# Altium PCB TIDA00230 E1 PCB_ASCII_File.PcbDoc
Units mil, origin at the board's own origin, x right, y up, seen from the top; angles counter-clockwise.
Board outline 1000 x 1000 mil, 2 copper layers (Top Layer, Bottom Layer), stack 62 mil thick; 50 components, 26 nets, 149 pads, 37 vias.
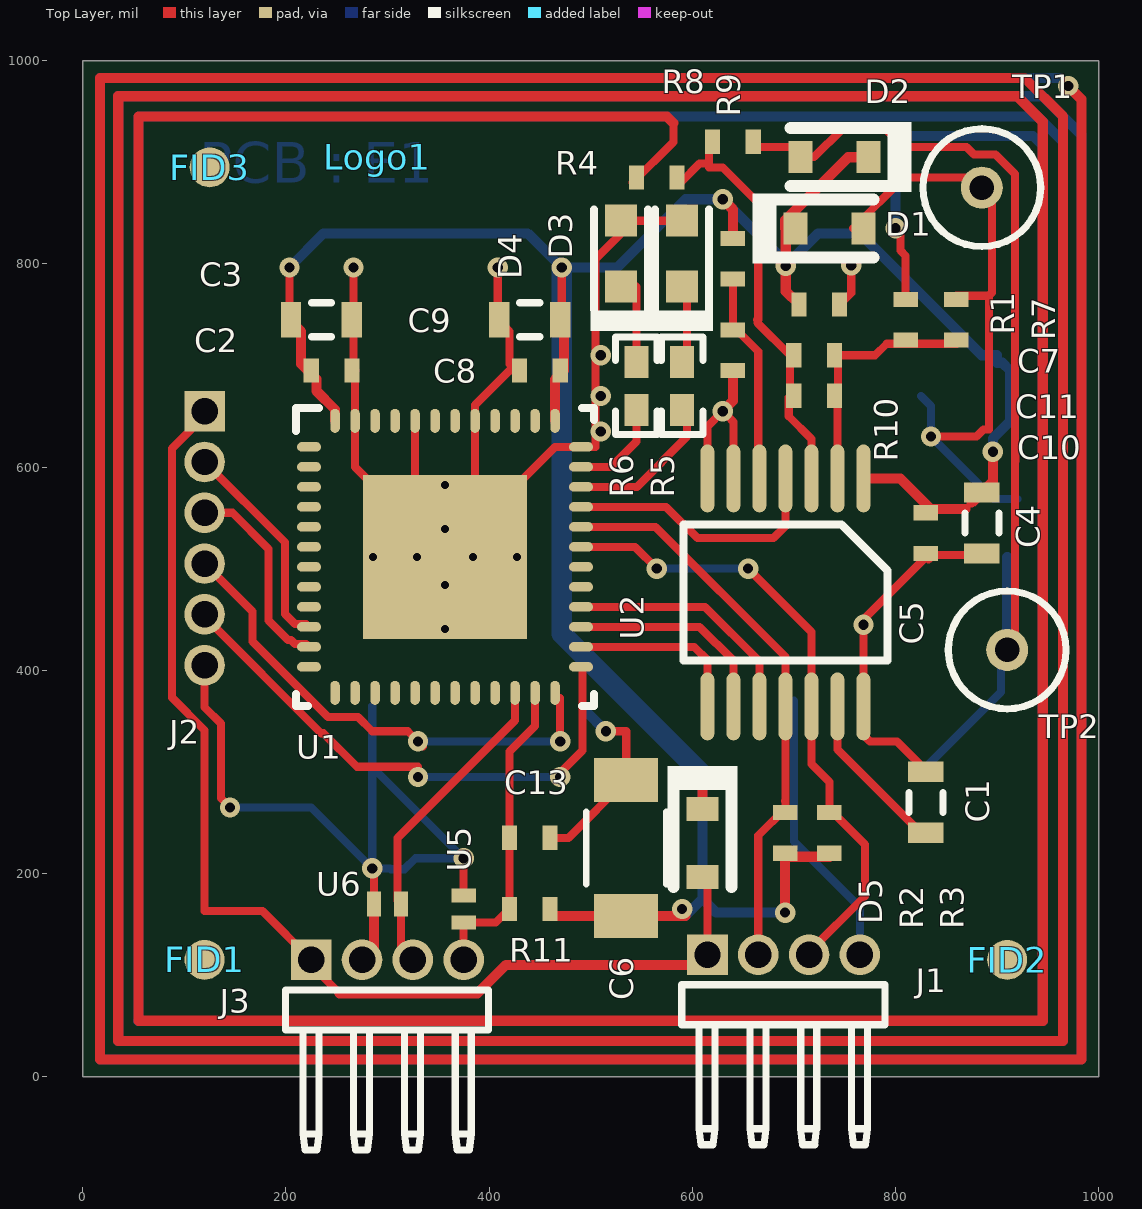
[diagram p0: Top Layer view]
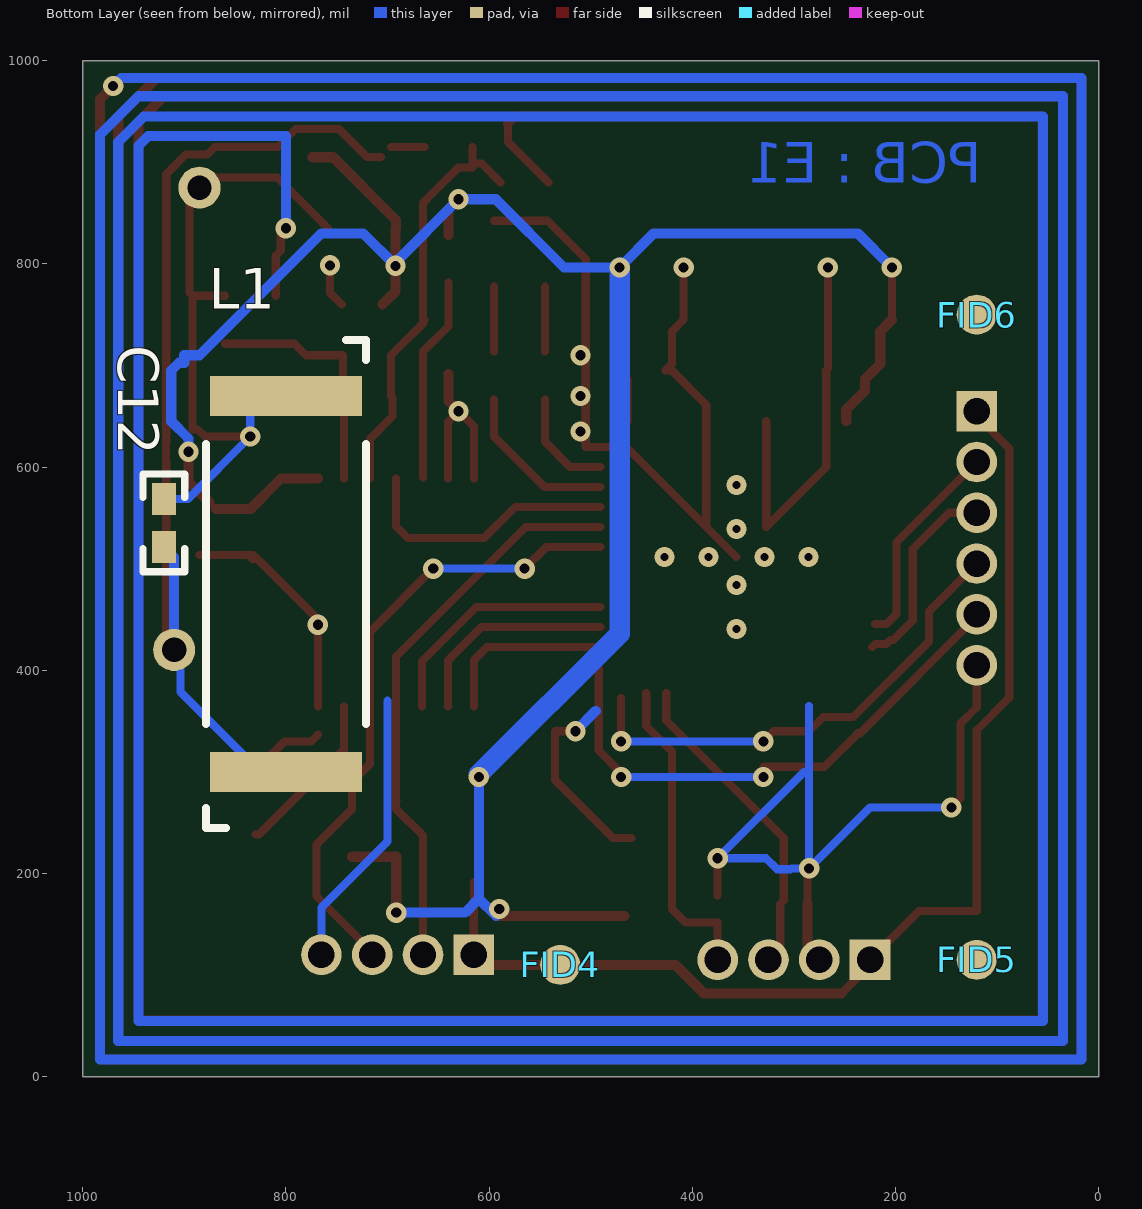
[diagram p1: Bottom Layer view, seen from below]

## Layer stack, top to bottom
Top Layer: signal copper 1.4
Dielectric: core 59.2, FR-4, Dk 4.8
Bottom Layer: signal copper 1.4

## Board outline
0,0 0,1000 1000,1000 1000,0

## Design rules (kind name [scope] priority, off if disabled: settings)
AssemblyTestPointUsage [All] p0 off: scope1count=1 scope1_0_kind=Board scope1_0_value=Board scope2count=1 scope2_0_kind=Board scope2_0_value=Board commentlength=0
AssemblyTestPointUsage [All] p1 off:
AssemblyTestpoint [All] p0 off: scope1count=1 scope1_0_kind=Board scope1_0_value=Board scope2count=1 scope2_0_kind=Board scope2_0_value=Board commentlength=0
AssemblyTestpoint [All] p1 off: testpointundercomponent=TRUE minsize=40 maxsize=100 preferedsize=60 minholesize=0 maxholesize=40 preferedholesize=32 testpointgrid=1 usegrid=TRUE gridtolerance=0.01 allowsidetop=TRUE allowsidebottom=TRUE
Clearance [All] p0: scope1count=1 scope1_0_kind=Board scope1_0_value=Board scope2count=1 scope2_0_kind=Board scope2_0_value=Board commentlength=0 gap=4.92
Clearance [All] p1: gap=4.92
ComponentClearance [All] p0: scope1count=1 scope1_0_kind=Board scope1_0_value=Board scope2count=1 scope2_0_kind=Board scope2_0_value=Board commentlength=0 gap=10 collisioncheckmode=3
DiffPairsRouting [All] p0: scope1count=1 scope1_0_kind=Board scope1_0_value=Board scope2count=1 scope2_0_kind=Board scope2_0_value=Board commentlength=0
DiffPairsRouting [All] p1: maxlimit=393.7 minlimit=4.92 mostfreqgap=5.91 maxuncoupledlength=500
FabricationTestPointUsage FabricationTestPointUsage_1 [All] p0 off: scope1count=1 scope1_0_kind=Board scope1_0_value=Board scope2count=1 scope2_0_kind=Board scope2_0_value=Board commentlength=0 valid=0 allowmultiple=FALSE
FabricationTestPointUsage FabricationTestPointUsage_1 [All] p1 off: valid=0 allowmultiple=FALSE
FabricationTestpoint FabricationTestpoint_1 [All] p0 off: scope1count=1 scope1_0_kind=Board scope1_0_value=Board scope2count=1 scope2_0_kind=Board scope2_0_value=Board commentlength=0 side=3 testpointundercomponent=TRUE minsize=40 maxsize=100 preferedsize=60 minholesize=0 maxholesize=40 preferedholesize=32 testpointgrid=1
FabricationTestpoint FabricationTestpoint_1 [All] p1 off: side=3 testpointundercomponent=TRUE minsize=40 maxsize=100 preferedsize=60 minholesize=0 maxholesize=40 preferedholesize=32 testpointgrid=1 allowsidetop=TRUE allowsidebottom=TRUE usegrid=TRUE gridtolerance=0.01
FanoutControl Fanout_BGA [All] p0 off: scope1count=1 scope1_0_kind=Board scope1_0_value=Board scope2count=1 scope2_0_kind=Board scope2_0_value=Board commentlength=69 // Protel DXP Scope 1 Expression Was: IsBGA   Fanout_BGA (Default Rule)
FanoutControl Fanout_LCC [All] p0 off: scope1count=1 scope1_0_kind=Board scope1_0_value=Board scope2count=1 scope2_0_kind=Board scope2_0_value=Board commentlength=69 // Protel DXP Scope 1 Expression Was: IsLCC   Fanout_LCC (Default Rule)
FanoutControl Fanout_SOIC [All] p0 off: scope1count=1 scope1_0_kind=Board scope1_0_value=Board scope2count=1 scope2_0_kind=Board scope2_0_value=Board commentlength=71 // Protel DXP Scope 1 Expression Was: IsSOIC   Fanout_SOIC (Default Rule)
FanoutControl Fanout_Small [All] p0 off: scope1count=1 scope1_0_kind=Board scope1_0_value=Board scope2count=1 scope2_0_kind=Board scope2_0_value=Board commentlength=84 // Protel DXP Scope 1 Expression Was: (CompPinCount < 5)   Fanout_Small (Default Rule)
FanoutControl Fanout_Default [All] p0: scope1count=1 scope1_0_kind=Board scope1_0_value=Board scope2count=1 scope2_0_kind=Board scope2_0_value=Board commentlength=30 // Fanout_Default (Default Rule)
Height [All] p0: scope1count=1 scope1_0_kind=Board scope1_0_value=Board scope2count=1 scope2_0_kind=Board scope2_0_value=Board commentlength=0
HoleSize [All] p0: scope1count=1 scope1_0_kind=Board scope1_0_value=Board scope2count=1 scope2_0_kind=Board scope2_0_value=Board commentlength=0 absolutevalues=TRUE maxlimit=236.22 minlimit=7.87 maxpercent=80.000 minpercent=20.000
HoleSize FabricationTestpoint [All] p0 off: scope1count=1 scope1_0_kind=Board scope1_0_value=Board scope2count=1 scope2_0_kind=Board scope2_0_value=Board commentlength=0 absolutevalues=TRUE maxlimit=100 minlimit=1 maxpercent=80.000 minpercent=20.000
HoleSize FabricationTestPointUsage [All] p0 off: scope1count=1 scope1_0_kind=Board scope1_0_value=Board scope2count=1 scope2_0_kind=Board scope2_0_value=Board commentlength=0 absolutevalues=TRUE maxlimit=100 minlimit=1 maxpercent=80.000 minpercent=20.000
HoleSize [All] p1: absolutevalues=TRUE maxlimit=236.22 minlimit=7.87 maxpercent=80.000 minpercent=20.000
HoleSize FabricationTestpoint [All] p2 off: absolutevalues=TRUE maxlimit=100 minlimit=1 maxpercent=80.000 minpercent=20.000
HoleSize FabricationTestPointUsage [All] p3 off: absolutevalues=TRUE maxlimit=100 minlimit=1 maxpercent=80.000 minpercent=20.000
HoleToHoleClearance [All] p0: scope1count=1 scope1_0_kind=Board scope1_0_value=Board scope2count=1 scope2_0_kind=Board scope2_0_value=Board commentlength=0
LayerPairs [All] p0: scope1count=1 scope1_0_kind=Board scope1_0_value=Board scope2count=1 scope2_0_kind=Board scope2_0_value=Board commentlength=0 enforce=TRUE
MinimumSolderMaskSliver [All] p0: scope1count=1 scope1_0_kind=Board scope1_0_value=Board scope2count=1 scope2_0_kind=Board scope2_0_value=Board commentlength=0
MinimumSolderMaskSliver MinimumSolderMaskSliver_mcv [All] p0: scope1count=1 scope1_0_kind=Board scope1_0_value=Board scope2count=1 scope2_0_kind=Board scope2_0_value=Board commentlength=0
MinimumSolderMaskSliver MinimumSolderMaskSliver_mcv [All] p2: minsoldermaskwidth=5
NetAntennae [All] p0: scope1count=1 scope1_0_kind=Board scope1_0_value=Board scope2count=1 scope2_0_kind=Board scope2_0_value=Board commentlength=0
PasteMaskExpansion [All] p0: scope1count=1 scope1_0_kind=Board scope1_0_value=Board scope2count=1 scope2_0_kind=Board scope2_0_value=Board commentlength=0 expansion=0
PlaneClearance [All] p0: scope1count=1 scope1_0_kind=Board scope1_0_value=Board scope2count=1 scope2_0_kind=Board scope2_0_value=Board commentlength=0 clearance=19.68
PlaneClearance [All] p1: clearance=19.68
PlaneConnect [All] p0: scope1count=1 scope1_0_kind=Board scope1_0_value=Board scope2count=1 scope2_0_kind=Board scope2_0_value=Board commentlength=0 planeconnectstyle=Relief reliefexpansion=15.75 reliefentries=4 reliefconductorwidth=5.91 reliefairgap=5.91
PlaneConnect [All] p1: planeconnectstyle=Relief reliefexpansion=15.75 reliefentries=4 reliefconductorwidth=5.91 reliefairgap=5.91
PolygonConnect [All] p0: scope1count=1 scope1_0_kind=Board scope1_0_value=Board scope2count=1 scope2_0_kind=Board scope2_0_value=Board commentlength=0 connectstyle=Relief reliefconductorwidth=5.91 reliefentries=4 polygonreliefangle="90 Angle"
PolygonConnect [All] p1: connectstyle=Relief reliefconductorwidth=5.91 reliefentries=4 polygonreliefangle="90 Angle" airgapwidth=10
RoutingCorners [All] p0: scope1count=1 scope1_0_kind=Board scope1_0_value=Board scope2count=1 scope2_0_kind=Board scope2_0_value=Board commentlength=0 cornerstyle=45-Degree minsetback=49.21 maxsetback=49.21
RoutingCorners [All] p1: cornerstyle=45-Degree minsetback=49.21 maxsetback=49.21
RoutingLayers [All] p0: scope1count=1 scope1_0_kind=Board scope1_0_value=Board scope2count=1 scope2_0_kind=Board scope2_0_value=Board commentlength=0 top layer=Automatic bottom layer=Automatic
RoutingPriority [All] p0: scope1count=1 scope1_0_kind=Board scope1_0_value=Board scope2count=1 scope2_0_kind=Board scope2_0_value=Board commentlength=0
RoutingTopology [All] p0: scope1count=1 scope1_0_kind=Board scope1_0_value=Board scope2count=1 scope2_0_kind=Board scope2_0_value=Board commentlength=0 topology=Shortest
RoutingVias [All] p0: scope1count=1 scope1_0_kind=Board scope1_0_value=Board scope2count=1 scope2_0_kind=Board scope2_0_value=Board commentlength=0 holewidth=11.81 width=23.62 viastyle="Through Hole" minholewidth=7.87 minwidth=17.72 maxholewidth=17.72 maxwidth=29.53
RoutingVias [All] p1: holewidth=11.81 width=23.62 viastyle="Through Hole" minholewidth=7.87 minwidth=17.72 maxholewidth=17.72 maxwidth=29.53
ShortCircuit [All] p0: scope1count=1 scope1_0_kind=Board scope1_0_value=Board scope2count=1 scope2_0_kind=Board scope2_0_value=Board commentlength=0 allowed=FALSE
SilkToSilkClearance [All] p0: scope1count=1 scope1_0_kind=Board scope1_0_value=Board scope2count=1 scope2_0_kind=Board scope2_0_value=Board commentlength=0
SilkscreenOverComponentPads [All] p0: scope1count=1 scope1_0_kind=Board scope1_0_value=Board scope2count=1 scope2_0_kind=Board scope2_0_value=Board commentlength=0
SilkscreenOverComponentPads SilkscreenOverComponentPads_mcv [All] p0: scope1count=1 scope1_0_kind=Board scope1_0_value=Board scope2count=1 scope2_0_kind=Board scope2_0_value=Board commentlength=0
SilkscreenOverComponentPads SilkscreenOverComponentPads_mcv [All] p1: minsilkscreentomaskgap=5
SilkscreenOverComponentPads [All] p2: minsilkscreentomaskgap=10
SolderMaskExpansion [All] p0: scope1count=1 scope1_0_kind=Board scope1_0_value=Board scope2count=1 scope2_0_kind=Board scope2_0_value=Board commentlength=0 expansion=2.95
SolderMaskExpansion [All] p1: expansion=2.95
UnRoutedNet [All] p0: scope1count=1 scope1_0_kind=Board scope1_0_value=Board scope2count=1 scope2_0_kind=Board scope2_0_value=Board commentlength=0
Width [All] p0: scope1count=1 scope1_0_kind=Board scope1_0_value=Board scope2count=1 scope2_0_kind=Board scope2_0_value=Board commentlength=0 maxlimit=393.7 minlimit=4.92 preferedwidth=5.91
Width [All] p1: maxlimit=393.7 minlimit=4.92 preferedwidth=5.91
18 further rules are at their usual default settings.

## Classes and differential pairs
component class Logo: Logo1
component class "TIDA00230 Hardware_ANSI-B": FID1 FID2 FID3 FID4 FID5 FID6 Logo1 ZZ1 ZZ2 ZZ3 ZZ4
component class FiducialMark: FID1 FID2 FID3 FID4 FID5 FID6
component class AssemblyNote: ZZ1 ZZ2 ZZ3 ZZ4
component class "TIDA00230 Sheet 1": C1 C2 C3 C4 C5 C6 C7 C8 C9 C10 C11 C12 C13 D1 D2 D3 D4 D5 J1 J2 J3 L1 R1 R2 R3 R4 R5 R6 R7 R8 R9 R10 R11 TP1 TP2 U1 U2 U5 U6

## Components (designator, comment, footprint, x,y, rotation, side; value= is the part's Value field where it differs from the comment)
C1 "GRM188R71E474KA12D" 0603S 830,270 r90 top
C2 "GRM155R71C104KA88D" 0402S 245,695 r0 top
C3 "GRM188R71C105KA12D" 0603S 235,745 r0 top
C4 "GRM188R71C105KA12D" 0603S 885,545 r270 top
C5 "GRM155R71C104KA88D" 0402S 830,535 r270 top
C6 "C3216X5R1A107M160AC" 1206_190 535,225 r90 top
C7 "CL05A106MP5NUNC" 0402S 725,760 r0 top
C8 "GRM155R71C104KA88D" 0402S 450,695 r180 top
C9 "GRM188R71C105KA12D" 0603S 440,745 r180 top
C10 "GRM1555C1H390JA01D" 0402S 720,670 r180 top
C11 "GRM1555C1E6R2CA01D" 0402S 720,710 r180 top
C12 "GRM1555C1H390JA01D" 0402 920,545 r270 bottom
C13 "DNP" 0402S 440,235 r0 top
D1 "CDBU0130L" SOD-523F 735,835 r0 top
D2 "CDBU0130L" SOD-523F 740,905 r180 top
D3 "SML-311DTT86" SML-31_Orange 590,810 r90 top
D4 "SML-311DTT86" SML-31_Orange 530,810 r90 top
D5 "CDBU0130L" SOD-523F 610,230 r270 top
FID1 "Fiducial" Fiducial10-20 120,115 r0 top
FID2 "Fiducial" Fiducial10-20 910,115 r0 top
FID3 "Fiducial" Fiducial10-20 125,895 r0 top
FID4 "Fiducial" Fiducial10-20 530,110 r180 bottom
FID5 "Fiducial" Fiducial10-20 120,115 r180 bottom
FID6 "Fiducial" Fiducial10-20 120,750 r180 bottom
J1 "I2C Interface Connector" Sullins_GRPB041VWCN 690,120 r0 top
J2 "SPI Connector (Back-up)" Sullins_GRPB061VWCN 120,530 r270 top
J3 "Debug and Programming Interface" Sullins_GRPB041VWCN 300,115 r0 top
L1 "NFC Antenna - 3uH" PREMO_SDTR1103-HF2 800,485 r90 bottom
Logo1 "Texas Instruments" TI_Symbol_Overlay_Small 290,905 r0 top
R1 "CRCW04020000Z0ED" 0402S 810,745 r270 top
R2 "CRCW04024K75FKED" 0402S 691.41,240 r270 top
R3 "CRCW04024K75FKED" 0402S 735,240 r270 top
R4 "CRCW04020000Z0ED" 0402S 565,885 r180 top
R5 "CRCW04021K00FKED" 0402 590,680 r270 top
R6 "CRCW04021K00FKED" 0402 545,680 r270 top
R7 "CRCW04020000Z0ED" 0402S 860,745 r270 top
R8 "CRCW04020000Z0ED" 0402S 640,920 r180 top
R9 "CRCW04020000Z0ED" 0402S 640,805 r90 top
R10 "CRCW04020000Z0ED" 0402S 640,715 r90 top
R11 "CRCW040247K0JNED" 0402S 440,165 r0 top
TP1 "5000" Keystone5000 885,875 r0 top
TP2 "5000" Keystone5000 910,420 r0 top
U1 "MSP430FR5969IRGZ" RGZ0048B 356.69,511.61 r0 top
U2 "RF430CL330HCPW" PW0014A_N 691.69,476.61 r270 top
U5 "TPD1E10B06DPYR" DPY0002A_N 375,165 r90 top
U6 "TPD1E10B06DPYR" DPY0002A_N 300,170 r180 top
ZZ1 "This Assembly Note is for PCB labels only" AssemblyNoteLabel 265,3938 r0 top
ZZ2 "These assemblies are ESD sensitive, ESD precautions shall be observed." AssemblyNote 265,3829.11 r0 top
ZZ3 "These assemblies must be clean and free from flux and all contaminants. Use of no clean flux is not acceptable." AssemblyNote 265,3740.56 r0 top
ZZ4 "These assemblies must comply with workmanship standards IPC-A-610 Class 2, unless otherwise specified." AssemblyNote 265,3652 r0 top

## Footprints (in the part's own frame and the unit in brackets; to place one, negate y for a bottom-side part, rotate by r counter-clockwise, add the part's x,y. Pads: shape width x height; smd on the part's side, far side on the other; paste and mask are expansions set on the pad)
0402 [mm] "0402 from SM-752 data"
  rect 0.8x0.6 smd: 1(-0.6,0) 2(0.6,0)
  silkscreen extent -1.22,-0.52 1.22,0.52
0402S [mil] "Based on C0402S footprint from PADS legacy"
  rect 15x24 smd: 1(-20,0) 2(20,0)
0603S [mil]
  rect 20x35 smd: 1(-30,0) 2(30,0)
  silkscreen extent -10,-17 10,17
1206_190 [mm] "1206_190"
  rect 1.1x1.6 smd: 1(-1.7,0) 2(1.7,0)
  silkscreen extent -0.9,-1 0.9,1
AssemblyNote [mil] "Assembly Note"
AssemblyNoteLabel [mil] "Assembly Note for PCB Labels"
DPY0002A_N [mm] "DFN, 2-Leads, Body 1.0x0.6x0.4mm, IPC Medium Density"
  rect 0.35x0.62 smd: 1(-0.34,0) 2(0.34,0)
Fiducial10-20 [mm]
  round 1 smd paste-0.5 mask+0.5: 1(0,0)
Keystone5000 [mm] "For Keystone 500x miniature loop terminals"
  round 1.05 hole 0.61: 1(0,0)
  silkscreen extent -1.47,-1.47 1.47,1.47
PREMO_SDTR1103-HF2 [mm] "Premo"
  rect 1x3.8 smd: 1(-4.7,0) 2(4.7,0)
  silkscreen extent -6.1,-2 6.1,2
PW0014A_N [mm] "TSOP, 14-Leads, Body 5x4.4mm, Pitch 0.65mm, IPC Medium Density"
  oval 1.7x0.35 smd: 1(-2.85,1.95) 2(-2.85,1.3) 3(-2.85,0.65) 4(-2.85,0) 5(-2.85,-0.65) 6(-2.85,-1.3) 7(-2.85,-1.95) 8(2.85,-1.95) 9(2.85,-1.3) 10(2.85,-0.65) 11(2.85,0) 12(2.85,0.65) 13(2.85,1.3) 14(2.85,1.95)
  silkscreen extent -1.7,-2.55 1.7,2.55
RGZ0048B [mm] "QFN, 48-Leads, Body 7x7mm, Pitch 0.5mm, Thermal Pad 5.15x5.15mm, TI Recommended"
  oval 0.6x0.24 smd: 1(-3.4,2.75) 2(-3.4,2.25) 3(-3.4,1.75) 4(-3.4,1.25) 5(-3.4,0.75) 6(-3.4,0.25) 7(-3.4,-0.25) 8(-3.4,-0.75) 9(-3.4,-1.25) 10(-3.4,-1.75) 11(-3.4,-2.25) 12(-3.4,-2.75) 25(3.4,-2.75) 26(3.4,-2.25) 27(3.4,-1.75) 28(3.4,-1.25) 29(3.4,-0.75) 30(3.4,-0.25) 31(3.4,0.25) 32(3.4,0.75) 33(3.4,1.25) 34(3.4,1.75) 35(3.4,2.25) 36(3.4,2.75)
  oval 0.24x0.6 smd: 13(-2.75,-3.4) 14(-2.25,-3.4) 15(-1.75,-3.4) 16(-1.25,-3.4) 17(-0.75,-3.4) 18(-0.25,-3.4) 19(0.25,-3.4) 20(0.75,-3.4) 21(1.25,-3.4) 22(1.75,-3.4) 23(2.25,-3.4) 24(2.75,-3.4) 37(2.75,3.4) 38(2.25,3.4) 39(1.75,3.4) 40(1.25,3.4) 41(0.75,3.4) 42(0.25,3.4) 43(-0.25,3.4) 44(-0.75,3.4) 45(-1.25,3.4) 46(-1.75,3.4) 47(-2.25,3.4) 48(-2.75,3.4)
  rect 4.1x4.1 smd paste-2.575: 49(0,0)
  silkscreen extent -3.72,-3.72 3.72,3.72
SML-31_Orange [mm] "Rohm"
  rect 0.8x0.8 smd: 1(-0.825,0) 2(0.825,0)
  silkscreen extent -1.93,-0.77 1.1,0.77
SOD-523F [mm] "COMCHIP"
  rect 0.6x0.8 smd paste-0.05: 1(-0.85,0) 2(0.85,0)
  silkscreen extent -1.92,-0.87 1.1,0.87
Sullins_GRPB041VWCN [mil] "Sullins"
  rect 40x40 hole 26 mask+3: 1(-75,0)
  round 40 hole 26 mask+3: 2(-25,0) 3(25,0) 4(75,0)
  silkscreen extent -100,-187 100,-30
Sullins_GRPB061VWCN [mil] "Sullins"
  rect 40x40 hole 26 mask+3: 1(-125,0)
  round 40 hole 26 mask+3: 2(-75,0) 3(-25,0) 4(25,0) 5(75,0) 6(125,0)
TI_Symbol_Overlay_Small [mil]

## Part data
C1: "CAP, CERM, 0.47uF, 25V, +/-10%, X7R, 0603"
C2 C5 C8: "CAP, CERM, 0.1uF, 16V, +/-10%, X7R, 0402"
C3 C4 C9: "CAP, CERM, 1uF, 16V, +/-10%, X7R, 0603"
C6: "CAP, CERM, 100uF, 10V, +/-20%, X5R, 1206_190"
C7: "CAP, CERM, 10uF, 10V, +/-20%, X5R, 0402"
C10 C12: "CAP, CERM, 39pF, 50V, +/-5%, C0G/NP0, 0402"
C11: "CAP, CERM, 6.2pF, 25V, +/-5%, C0G/NP0, 0402"
C13: library part GRM155R70J222KA01D, "CAP, CERM, 2200pF, 6.3V, +/-10%, X7R, 0402"
D1 D2 D5: "Diode, Schottky, 35V, 0.1A, SOD-523F"
D3 D4: "LED, Orange, SMD"
FID1 FID2 FID3 FID4 FID5 FID6: "Fiducial mark.  There is nothing to buy or mount."
J1 J3: library part GRPB041VWCN-RC, "Header, 50mil, 4x1, R/A, TH"
J2: library part GRPB061VWCN-RC, "Header, 50mil, 6x1, R/A, TH"
L1: library part SDTR1103-HF2-0003K, "Inductor, Wirewound, 3uH, 0.46 ohm, SMD"
Logo1: library part TI_Logo, "Texas Instrument Corporate Signature"
R1 R4 R7 R8 R9 R10: "RES, 0 ohm, 5%, 0.063W, 0402"
R2 R3: "RES, 4.75k ohm, 1%, 0.063W, 0402"
R5 R6: "RES, 1.00k ohm, 1%, 0.063W, 0402"
R11: "RES, 47k ohm, 5%, 0.063W, 0402"
TP1 TP2: "Test Point, Miniature, Red, TH"
U1: "Mixed Signal Microcontroller, RGZ0048B"
U2: "DYNAMIC NFC INTERFACE TRANSPONDER, PW0014A"
U5 U6: "ESD in 0402 Package with 10 pF Capacitance and 6 V Breakdown, 1 Channel, -40 to +125 degC, 2-pin X2SON (DPY), Green (RoHS & no Sb/Br)"
ZZ1: library part AssemblyNoteLabel
ZZ2 ZZ3 ZZ4: library part AssemblyNote

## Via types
v1: diameter 20, hole 10, Top Layer to Bottom Layer, 29 vias
v2: diameter 19.68, hole 7.87, Top Layer to Bottom Layer, 8 vias

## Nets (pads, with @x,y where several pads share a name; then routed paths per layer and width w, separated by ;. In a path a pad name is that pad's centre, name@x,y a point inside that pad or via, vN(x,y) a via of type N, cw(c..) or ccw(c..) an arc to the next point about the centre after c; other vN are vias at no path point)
ANT1: C10.1 C11.1 R1.2 R7.2 U2.2 | length 242.6
  Top Layer w8: U2.2 742.87,669.25 743.62,670 743.62,710 780,710 791.38,721.38 810,721.38 R7.2@860,721.38
ANT2: C10.2 C11.2 R4.1 R8.2 U2.3 | length 410.6
  Top Layer w7.99: 616.38,898.62 R8.2@616.38,915 ; 655,870 665,860
  Top Layer w8: R4.1@588.62,880 607.24,898.62 616.38,898.62 ; 616.38,895 630,895 655,870 ; 665,860 665,745 663.81,745 664.41,744.41 664.41,741.97 696.38,710 696.38,670 695,668.62 695,650 717.28,627.72 U2.3
GND_SYSTEM: C1.2 C2.2 C3.2 C4.2 C5.2 C6.2 C7.2 C8.2 C9.2 C13.2 D3.2 D4.2 J1.4 J2.6 J3.2 R10.1 U1.36 U1.41 U1.44 U1.47 U1.49 U2.6 U2.7 U2.14 U5.2 U6.2 | length 2948
  Top Layer w8: J2.6 120,363.63 136,347.63 136,274 v1(145,265) ; v1(266.5,796.5) 266.5,697.13 C2.2@268.62,695 ; C2.2@268.11,694.49 U1.47 268.11,600.2 327.17,541.14 U1.44 ; v1(285,205) 286.61,203.39 U6.2 ; U1.49 U1.49@386.22,541.14 ; U5.2 v1(375,215) ; v1(408.5,796.5) 408.5,745 420,733.5 420,701.38 426.38,695 420,695 386.22,661.22 U1.41 U1.49@386.22,541.14 ; C13.2 478.07,235 C6.2 535,340 v1(515,340) ; D3.2@595,842.48 542.48,842.48 504.88,804.88 504.88,619.88 U1.36 464.96,619.88 U1.49@386.22,541.14 ; U2.7 614.92,639.92 v1(630,655) ; v1@635.51,649.49 640.51,644.49 U2.6 ; C7.2 756.5,771.5 v1(756.5,798.5) ; U2.14@768.46,336.54 775,330 801.5,330 C1.2@830,301.5 ; U2.14 v1(768.46,444.84) ; v1@768.46,449.84 C5.2@830,511.38 ; C5.2@832.13,513.5 C4.2@885,513.5 ; C5.2@832.5,508.88 C5.2@835,511.38
  Top Layer w10: J3.2@286.61,126.61 U6.2 ; v1(630,655) 640,665 R10.1@640,691.38
  Bottom Layer w8: v1(145,265) 225,265 v1(285,205) ; 285,365 v1(285,205) ; 290,300 v1(375,215) 327.43,215 316.63,204.2 303.37,204.2 302.57,205 v1(285,205) ; 700,370 700,231.41 765,166.41 J1.4
  Bottom Layer w10: 495,360 v1(515,340)
  other v1: 510,635 510,670 510,710
  other v2: 356.69,440.75 356.69,484.05 285.83,511.61 329.13,511.61 384.25,511.61 427.56,511.61 356.69,539.17 356.69,582.48
I2C_SCL: J1.2 R2.1 U1.32 U2.11 | length 568.4
  Top Layer w8: U1.32 563.86,541.14 691.69,413.31 U2.11 R2.1@691.69,263.62 ; J1.2@665,110 665,237.22 R2.1@691.41,263.62 ; 691.41,271.41 691.41,271.5
I2C_SDA: J1.3 R3.1 U1.31 U2.12 | length 633.8
  Top Layer w8: U1.31 543.54,521.46 v1(565,500) ; v1(655,500) 717.28,437.72 U2.12 717.28,307.72 735,290 735,263.62 770,228.62 770,177.52 715,122.52 J1.3@715,110
  Bottom Layer w8: v1(565,500) v1(655,500)
NetC1_1: C1.1 U2.13 | length 164
  Top Layer w8: U2.13 742.87,322.13 826.5,238.5 C1.1@830,238.5
NetC12_1: C12.1 D1.2 L1.2 R7.1 TP1.1 | length 630.9
  Top Layer w8: D1.2@758.46,835 808.46,885 875,885 TP1.1 895,865 895,771.62 892,768.62 ; v1(835,630) 879.75,630 886.75,637 892,637 892,768.62 ; R7.1@860,768.62 892,768.62
  Bottom Layer w8: L1.2@825,670.04 835,660.04 835,640.35 ; v1(835,630) 896.38,568.62 C12.1
NetC12_2: C12.2 D2.2 L1.1 R8.1 TP2.1 | length 975.2
  Top Layer w7.99: TP2.1@917.67,433.93 917.67,605.7 917.86,605.89 917.86,624.11 917.67,624.3 917.67,753.06
  Top Layer w8: R8.1@663.62,915 D2.2@696.54,915 ; D2.2 720,905 747.75,932.75 790.25,932.75 807.99,915 870,915 877.33,907.67 898.53,907.67 917.67,888.53 917.67,753.06
  Bottom Layer w8: L1.1@825,299.96 903.74,378.7 TP2.1@903.74,420
  Bottom Layer w10: TP2.1@903.74,420 910,426.26 C12.2@910,511.38
NetD3_1: D3.1 R5.1 | length 63.9
  Top Layer w8: R5.1@595,713.62 D3.1@595,777.52
NetD4_1: D4.1 R6.1 | length 63.9
  Top Layer w8: R6.1@545,713.62 D4.1@545,777.52
NetR5_2: R5.2 U1.34 | length 161.3
  Top Layer w8: U1.34 545.51,580.51 595,630 R5.2@595,666.38
NetR6_2: R6.2 U1.35 | length 106.1
  Top Layer w8: U1.35 520.2,600.2 545,625 R6.2@545,666.38
NetR9_1: R9.1 R10.2 U2.5 | length 201.8
  Top Layer w7.99: R9.1@640,781.38 640,738.62 665,713.62 U2.5@665,589.92
PCB_ANT: R1.1 R4.2 | length 22180.9
  Top Layer w7.99: R4.2@541.38,880 581.38,920 581.38,938.62 ; v1@805,830 805,813 810,808 R1.1@810,768.62
  Top Layer w10: 581.38,938.62 575,945 55,945 55,55 945,55 945,940 920,965 35,965 35,35 965,35 965,945 927,983 17,983 17,17 983,17 983,962 v1(970,975)
  Bottom Layer w10: 54.73,54.95 944.95,54.95 944.95,916.42 935.45,925.91 800,925.91 800,845 ; 54.86,55.08 54.86,944.89 ; 54.97,945 940,945 965,920 965,35 35,35 35,965 945,965 983,927 983,17 17,17 17,983 962,983 v1(970,975)
  other v1: 800,835
RF430_CS: U1.27 U2.9 | length 208.8
  Top Layer w8: U1.27 607.28,442.72 640.51,409.49 U2.9
RF430_IRQ: U1.26 U2.8 | length 175.4
  Top Layer w8: U1.26 601.97,423.03 614.92,410.08 U2.8
RF430_RST: U1.33 U2.4 | length 265.9
  Top Layer w8: U1.33 574.17,560.83 605,530 680,530 691.69,541.69 U2.4
RF430_SCK: U1.28 U2.10 | length 242.2
  Top Layer w8: U1.28 612.6,462.4 666.1,408.9 U2.10
SBWTCK: J3.3 U1.22 U6.1 | length 295.6
  Top Layer w8: U6.1@310,173.39 310,235 425.59,350.59 U1.22 ; J3.3@313.39,126.61 U6.1
SBWTDIO: C13.1 J3.4 R11.1 U1.23 U5.1 | length 310.4
  Top Layer w8: J3.4 U5.1 406.61,151.61 R11.1 C13.1 420,320 445.28,345.28 U1.23
UCSIA0_CLK: J2.3 U1.11 | length 198.8
  Top Layer w8: J2.3 147.37,555 183.02,519.35 183.02,448.85 202.19,429.68 205.14,429.68 208.82,425.99 219.87,425.99 U1.11
UCSIA0_SIMO: J2.4 U1.24 | length 489.6
  Top Layer w8: J2.4 167.02,457.98 167.02,428.42 241.5,353.94 271.06,353.94 285,340 320,340 v1(330,330) v1@335,325 ; v1(470,330) 470,372.72
  Bottom Layer w8: v1(330,330) v1(470,330)
UCSIA0_SOMI: J2.5 U1.25 | length 539.4
  Top Layer w8: J2.5 120,452.82 234.87,337.94 237.06,337.94 270,305 330,305 v1(330,295) ; v1(470,295) 470,298.89 492,320.89 U1.25@492,401.9
  Bottom Layer w8: v1(330,295) v1(470,295)
UCSIA0_STE: J2.2 U1.10 | length 207.2
  Top Layer w8: J2.2 199.02,525.98 199.02,455.47 208.82,445.68 U1.10@219.87,445.68
VCC: C2.1 C3.1 C4.1 C5.1 C6.1 C7.1 C8.1 C9.1 D1.1 D2.1 D5.1 R2.2 R3.2 R9.2 R11.2 U1.37 U1.48 U2.1 | length 2725.8
  Top Layer w8: C3.1@203.5,745 v1(203.5,796.5) ; C9.1@471.5,745 v1(471.5,796.5)
  Top Layer w10: C3.1@203.5,745 215,733.5 215,701.38 230,686.38 230,675 248.43,656.57 U1.48 ; U1.37 464.96,686.34 473.62,695 473.62,742.87 C9.1@471.5,745 ; R11.2@466.93,158.07 C6.1 v1@593.07,158.07 ; D5.1 v1(610,295) ; v1(630,863.62) 640,853.62 R9.2@640,828.62 ; v1(691.41,161.41) 691.41,216.38 R3.2@735,216.38 ; D1.1@691.54,835 691.54,843.07 753.46,905 D2.1 ; D1.1@692,834.54 v1(692,798) 692,773 C7.1 ; U2.1 804.8,588.82 835,558.62 868.62,558.62 ; C4.1@875,565 895.87,585.87 v1(895.87,615)
  Bottom Layer w10: v1(203.5,796.5) 237.01,830 437.99,830 v1(471.5,796.5) 526.25,796.5 593.37,863.62 v1(630,863.62) v1@692,801.62 ; v1@593.07,158.07 610,175 ; v1(610,295) 610,175 ; v1(691.41,161.41) 623.59,161.41 610,175 ; v1(692,798) 724,830 765,830 885,710 900,710 900,702.72 905.19,702.72 912.8,695.11 912.8,644.97 895.87,628.03 v1(895.87,615)
  Bottom Layer w20: v1(471.5,796.5) 471.5,436.03 v1@610,297.53
  other v1: 590,165
VCC_SYSTEM: D5.2 J1.1 J2.1 J3.1 | length 1137.3
  Top Layer w7.99: J1.1 615.07,120.07 615.07,167.25 615,167.32 D5.2@615,191.54
  Top Layer w8: J2.1 120,650.25 88,618.25 88,373 120,341 120,163.03 176.97,163.03 J3.1 225,110 253,82
  Top Layer w10: 253,82 388.67,82 416.67,110 605,110 J1.1
pads on no net: FID1.1 FID2.1 FID3.1 FID4.1 FID5.1 FID6.1 U1.1 U1.2 U1.3 U1.4 U1.5 U1.6 U1.7 U1.8 U1.9 U1.12 U1.13 U1.14 U1.15 U1.16 U1.17 U1.18 U1.19 U1.20 U1.21 U1.29 U1.30 U1.38 U1.39 U1.40 U1.42 U1.43 U1.45 U1.46

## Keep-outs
Keep-Out Layer:
  text ".Layer_Name" at 577,-858.49 h60

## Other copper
Top Layer:
  text ".Layer_Name" at 577,-858.49 h60
Bottom Layer:
  text "PCB : E1" at 115,880 h40
  text ".Layer_Name" at 577,-858.49 h60

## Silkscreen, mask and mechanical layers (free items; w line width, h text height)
Top Overlay:
  text ".Layer_Name" at 577,-858.49 h60
Bottom Overlay:
  text ".Layer_Name" at 577,-858.49 h60
Top Paste:
  text ".Layer_Name" at 577,-858.49 h60
Bottom Paste:
  text ".Layer_Name" at 577,-858.49 h60
Top Solder:
  text ".Layer_Name" at 577,-858.49 h60
  text ".Layer_Name" at 577,-858.49 h60
Bottom Solder:
  text ".Layer_Name" at 577,-858.49 h60
Drill Guide:
  text ".Layer_Name" at 577,-858.49 h60
M1 Board Outline:
  the board outline again, w10
  text ".Layer_Name" at 577,-858.49 h60
M2 Board Dimensions:
  rectangle: -0.5,-285.5 124.5,-160.5
  rectangle: 124.5,-410.5 499.5,-285.5
  lines w7: -0.5,-285.5 999.5,-285.5 ; 124.5,-410.5 124.5,-160.5 ; 249.5,-410.5 249.5,-160.5 ; 499.5,-410.5 499.5,-160.5 ; 749.5,-410.5 749.5,-160.5 ; -0.5,-410.5 999.5,-410.5 999.5,-160.5 -0.5,-160.5 -0.5,-410.5
  text ".Layer_Name" at 577,-858.49 h60
M3 3D STEP Top:
  text ".Layer_Name" at 577,-858.49 h60
M4 3D STEP Bottom:
  text ".Layer_Name" at 577,-858.49 h60
M5 Assembly Top:
  lines w10: -292,-930.17 6308,-930.17 ; -292,-726.83 6310,-726.83 ; -292,-523.5 -292,-1133.5 3713,-1133.5 6310,-1133.5 6310,-523.5 -291.5,-523.5 -291.5,-1133.5 1284,-1133.5 ; 2173,-1133.5 2173,-523.5 ; 3440,-726.83 3440,-523.5 ; 4280,-726.83 4280,-523.5 ; 4902,-1140 4902,-937.17
  text "COMPONENTS MARKED 'DNP' SHOULD NOT BE POPULATED." at 1153.5,-318.5 h60
  text "ASSEMBLY VARIANT:" at 1153,-434 h60
  text ".VariantName" at 2189,-434 h60
  text "PCB VIEWED FROM TOP SIDE" at -228.5,-655.67 h60
  text "BOARD #:" at 2248,-655.67 h60
  text ".PRJ_Number" at 2793.5,-655.67 h60
  text "REV:" at 3638,-655.67 h60
  text ".PCB_Rev" at 3929.5,-655.67 h60
  text "SVN REV:" at 4476,-655.67 h60
  text ".VersionControl_RevNumber" at 4982,-655.67 h60
  text "IGNORE ->" at -228.5,-858.49 h60
  text "PLOT NAME =" at -228.5,-1064.34 h60
  text ".plot_File_Name" at 577,-1064.34 h60
  text "GENERATED    :" at 2250,-1064.34 h60
  text ".Print_Date" at 3119.5,-1064.34 h60
  text ".Print_Time" at 3848.5,-1064.34 h60
  text "TEXAS INSTRUMENTS" at 5113,-1064.34 h60
M6 Assembly Bottom:
  lines w10: -292.5,-727.33 6309.5,-727.33 ; -290.5,-930.67 6309.5,-930.67 ; 1115.5,-1140.5 1115.5,-937.67 ; 1737.5,-727.33 1737.5,-524 ; 2577.5,-727.33 2577.5,-524 ; 3844.5,-1134 3844.5,-524 ; 4733.5,-1134 6309,-1134 6309,-524 -292.5,-524 -292.5,-1134 2304.5,-1134 6309.5,-1134 6309.5,-524
  text "COMPONENTS MARKED 'DNP' SHOULD NOT BE POPULATED." at 6102,-318 h60
  text ".VariantName" at 5058,-434 h60
  text "ASSEMBLY VARIANT:" at 6097,-434 h60
  text ".VersionControl_RevNumber" at 1035.5,-656.17 h60
  text "SVN REV:" at 1541.5,-656.17 h60
  text ".PCB_Rev" at 2088,-656.17 h60
  text "REV:" at 2379.5,-656.17 h60
  text ".PRJ_Number" at 3224,-656.17 h60
  text "BOARD #:" at 3769.5,-656.17 h60
  text "PCB VIEWED FROM BOTTOM SIDE" at 6246,-656.17 h60
  text "IGNORE ->" at 2547.85,-858.49 h60
  text "TEXAS INSTRUMENTS" at 904.5,-1064.84 h60
  text ".Print_Time" at 2169,-1064.84 h60
  text ".Print_Date" at 2898,-1064.84 h60
  text "GENERATED    :" at 3767.5,-1064.84 h60
  text ".plot_File_Name" at 5440.5,-1064.84 h60
  text "PLOT NAME =" at 6246,-1064.84 h60
M9 Title Sheet:
  lines w10: -491.5,1041.5 -291.5,1041.5 ; -491.5,3416.5 -291.5,3416.5 ; -491.5,5791.5 -291.5,5791.5 ; 2008.5,-1333.5 2008.5,-1133.5 ; 2008.5,7966.5 2008.5,8166.5 ; 4508.5,-1333.5 4508.5,-1133.5 ; 4508.5,7966.5 4508.5,8166.5 ; 6321,-1133.5 6321,-523.5 11303.5,-523.5 ; 7008.5,-1333.5 7008.5,-1133.5 ; 7008.5,7966.5 7008.5,8166.5 ; 9508.5,-1333.5 9508.5,-1133.5 ; 9508.5,7966.5 9508.5,8166.5 ; 11303.5,-1133.5 11303.5,-523.5 ; 11303.5,-823.5 14303.5,-823.5 ; 11303.5,-223.5 14303.5,-223.5 ; 11304.5,370.5 14304.5,370.5 ; 12008.5,-1333.5 12008.5,-1133.5 ; 12008.5,7966.5 12008.5,8166.5 ; 12808.5,-1123.5 12808.5,-523.5 ; 14303.5,-523.5 11303.5,-523.5 ; 14303.5,76.5 11303.5,76.5 ; 14308.5,66.5 14308.5,-1133.5 ; 14308.5,871 11304.5,871 11303.5,871 11303.5,370.5 11303.5,76.5 ; 14308.5,1041.5 14508.5,1041.5 ; 14308.5,3416.5 14508.5,3416.5 ; 14308.5,5791.5 14508.5,5791.5 ; 11303.5,-523.5 11303.5,76.5 ; 14308.5,-1133.5 14308.5,7966.5 -291.5,7966.5 -291.5,-1133.5 14308.5,-1133.5 ; -491.5,-1333.5 -491.5,8166.5 14508.5,8166.5 14508.5,-1333.5 -491.5,-1333.5
  text "1" at 739.84,8036.5 h70
  text "2" at 3235.5,8036.5 h70
  text "3" at 5724.84,8036.5 h70
  text "4" at 8231.51,8036.5 h70
  text "5" at 10730.5,8036.5 h70
  text "6" at 13235.5,8036.5 h70
  text "A" at -416.5,6893.5 h70
  text "A" at 14383.5,6893.5 h70
  text "B" at -416.5,4513.5 h70
  text "B" at 14383.5,4513.5 h70
  text "C" at -416.5,2138.5 h70
  text "C" at 14383.5,2138.5 h70
  text "PROJECT TITLE:" at 11343.5,277.5 h45
  text ".PRJ_Title" at 11393.5,144.17 h70
  text "DESIGNED FOR:" at 11343.5,-23.5 h45
  text ".PRJ_Customer" at 11393.5,-163.5 h70
  text "D" at -416.5,-231.5 h70
  text "D" at 14383.5,-231.5 h70
  text "FILE NAME:" at 11343.5,-323.5 h45
  text ".PCB_File_Name_No_Path" at 11393.5,-443.5 h70
  text "Texas Instruments (TI) and/or its licensors do not warrant the accuracy or completeness of this specification" at 6374,-605.34 h45
  text "ENGINEER:" at 11343.5,-613.5 h45
  text "LAYOUT BY:" at 12848.5,-613.5 h45
  text "or any information contained therein. TI and/or its licensors do not warrant that this design will meet" at 6329.01,-718 h45
  text ".PRJ_Engineer" at 11393.5,-768.49 h70
  text ".PCB_Layout" at 12899,-768.49 h70
  text "the specifications, will be suitable for your application or fit for any particular purpose, or will operate in" at 6329.01,-830.67 h45
  text ".Layer_Name" at 577,-858.49 h60
  text "ALTIUM DESIGNER VERSION:" at 12848.5,-923.5 h45
  text "an implementation. TI and/or its licensors do not warrant that the design is production worthy. You should" at 6329.01,-943.33 h45
  text "completely validate and test your design implementation to confirm the system functionality for your application." at 6374,-1056 h45
  text ".print_Scale" at 11393.5,-1056.83 h70
  text ".Application_BuildNumber" at 12899,-1056.83 h70
  text "1" at 739.84,-1263.5 h70
  text "2" at 3235.5,-1263.5 h70
  text "3" at 5724.84,-1263.5 h70
  text "4" at 8231.51,-1263.5 h70
  text "5" at 10730.5,-1263.5 h70
  text "6" at 13235.5,-1263.5 h70
M10 Fab Notes:
  drawing of 212 lines, arcs and shapes, not listed
  text "DESIGN INFORMATION" at 12381.02,6810 h60
  text "(REFER ALSO ARRAY/PANEL PROFILING INFORMATION)" at 12019.46,6648.29 h60
  text "BOARD SIZE" at 11333.46,6644 h60
  text "1000MIL" at 11795.78,6516.18 h60
  text "X" at 12301.46,6516.18 h60
  text "1000MIL" at 12532.78,6516.18 h60
  text "Number of Layers :" at 11736.46,6319 h60
  text "2" at 12831.27,6309 h60
  text "MIN. TRACK WIDTH:" at 11736.46,6180 h60
  text "8" at 12832.7,6180 h60
  text "MIL" at 12987.46,6180 h60
  text "MIN. CLEARANCE:" at 11736.46,6048 h60
  text "8" at 12832.7,6048 h60
  text "MIL" at 12987.46,6048 h60
  text "MIN. VIA PAD SIZE:" at 11736.46,5916 h60
  text "24" at 12802.71,5916 h60
  text "MIL" at 12987.46,5916 h60
  text "0.05mm (2MIL)" at 12431.46,5774.29 h60
  text "MINIMUM ANNULAR RING" at 11407.23,5770 h60
  text "EXTERNAL" at 13139.46,5770 h60
  text "PER" at 11607.23,5652 h60
  text "IPC-D-275 CLASS 2 LEVEL C" at 11827.23,5652 h60
  text "MIL, HOLES" at 13315.46,5539.71 h60
  text "+/-" at 12923,5539 h60
  text "+/-" at 13777,5539 h60
  text "REGISTRATION TOLERANCES:" at 11407.23,5534 h60
  text "METAL" at 12607,5534 h60
  text "5" at 13183.2,5534 h60
  text "3" at 14016.2,5534 h60
  text "MIL" at 14132.46,5534 h60
  text "MATERIAL:" at 11332.46,5324.54 h60
  text "FR-4 High Tg" at 12318.9,5184.21 h60
  text "FR-408" at 11753.46,5175.64 h60
  text "X" at 12165.46,5175.64 h60
  text "OTHER" at 13241.46,5175.64 h60
  text "62 MIL (1.6mm) +/-10%" at 12073.56,5012.92 h60
  text "THICKNESS:" at 11407.23,5008.64 h60
  text "X" at 11945.4,5008.64 h60
  text "OTHER" at 13358.46,5008.64 h60
  text "TOLERANCE:" at 11407.23,4850.64 h60
  text "X" at 12246.53,4850.64 h60
  text "ANSI IPC-6012 TYPE 3 CLASS 2" at 12433.48,4850.64 h60
  text "OTHER +/-" at 12433.46,4694.64 h60
  text "BOW & TWIST:" at 11407.23,4537.64 h60
  text "X" at 12246.53,4537.64 h60
  text "ANSI IPC-6012 TYPE 3 CLASS 2" at 12433.48,4537.64 h60
  text "OTHER +/-" at 12433.46,4379.13 h60
  text "COPPER THICKNESS (FINISHED):" at 11332.46,4243.64 h60
  text "1.4MIL (1oz)" at 12212.46,4090.92 h60
  text "2MIL (1.4oz)" at 12979.46,4090.92 h60
  text "2.8MIL (2oz)" at 13706.46,4090.92 h60
  text "OUTER:" at 11689.46,4086.64 h60
  text "X" at 12084,4086 h60
  text "1.4MIL (1oz)" at 12212.46,3933.92 h60
  text "2.8MIL (2oz)" at 12979.46,3933.92 h60
  text "N/A" at 13706,3934.29 h60
  text "INNER SIGNAL:" at 11400.38,3929.64 h60
  text "X" at 12085.42,3929.64 h60
  text "DRILLING:" at 11332.46,3790.64 h60
  text "REFERENCE:" at 11407.23,3673.64 h60
  text "X" at 12055.46,3673.64 h60
  text "AS SHOWN" at 12242.46,3673.64 h60
  text "X" at 12956.46,3673.64 h60
  text "NC_DRILL FILES" at 13093.46,3673.64 h60
  text "PTH MIN COPPER THICKNESS:" at 11407.23,3515.64 h60
  text "X" at 12757.46,3515.64 h60
  text "1MIL" at 12894.46,3515.64 h60
  text "OTHER" at 13391.46,3515.64 h60
  text "BOARD FINISH:" at 11332.46,3356.64 h60
  text "SILKSCREEN:" at 11487.68,3238.64 h60
  text "X" at 12436.46,3238.64 h60
  text "TOP" at 12562.46,3238.64 h60
  text "X" at 12946.46,3238.64 h60
  text "BOTTOM" at 13073.46,3238.64 h60
  text "SILKSCREEN COLOR:" at 11487.68,3071.64 h60
  text "X" at 12435.42,3071.64 h60
  text "WHITE" at 12562.46,3071.64 h60
  text "OTHER" at 13073.46,3071.64 h60
  text "SOLDER RESIST COLOR:" at 11487.68,2901.64 h60
  text "X" at 12055.42,2742.44 h60
  text "GREEN" at 12182.46,2742.44 h60
  text "BLUE" at 12773.46,2742.44 h60
  text "OTHER" at 13311.46,2742.44 h60
  text "IMMERSION GOLD (ENIG)" at 12393.46,2553.92 h60
  text "ENEPIG" at 13731,2550.64 h60
  text "SURFACE FINISH:" at 11332.46,2549.64 h60
  text "X" at 12206.51,2549.64 h60
  text "IMM. TIN/SILVER OR EQUIV" at 11662,2392.64 h60
  text "OTHER" at 13093.46,2392.64 h60
  text "ARRAY/PANEL:" at 11332.46,2213.64 h60
  text "CUT AND TRIM PER MECH LAYER 1" at 12393.46,2209.35 h60
  text "N.C. ROUTE" at 12393.46,2057.64 h60
  text "X" at 13072.46,2057.64 h60
  text "V. SCORE" at 13259.46,2057.64 h60
  text "CERTIFICATION:" at 11332.46,1920.64 h60
  text "MATERIALS AND WORKMANSHIP FOR ALL PCBS" at 12057.46,1920.64 h60
  text "TO MEET OR EXCEED THE REQUIREMENTS OF:" at 12057.46,1822.64 h60
  text "X" at 11683.96,1686.13 h60
  text "ANSI IPC-A-600F CLASS ->" at 11822.96,1686.13 h60
  text "X" at 13462.02,1686.13 h60
  text "2" at 13580.96,1686.14 h60
  text "1" at 13265.96,1684.64 h60
  text "3" at 13934.96,1684.64 h60
  text "X" at 11686.02,1526.64 h60
  text "UL 94V-0" at 11822.96,1526.64 h60
  text "X" at 12498.02,1526.64 h60
  text "RoHS" at 12634.96,1526.64 h60
  text "OTHER" at 13279.36,1526.64 h60
  text "PER ORDER" at 13676.42,1526.64 h60
  text "ADDITIONAL REQUIREMENTS:" at 11332.46,1385.64 h60
  text "MICROSECTION:" at 11407.23,1270.64 h60
  text "YES" at 12312.96,1270.64 h60
  text "REQUIRED" at 13174.46,1114.49 h60
  text "BARE BOARD ELEC. TEST:" at 11407.23,1111.64 h60
  text "NONE" at 12712.96,1111.64 h60
  text "X" at 13047.46,1111.64 h60
  text "PER ORDER" at 13766.46,1111.64 h60
  text "MANUFACTURER'S UL:" at 11407.23,954.64 h60
  text "RAIL" at 12572.96,950.35 h60
  text "METAL" at 13064.77,950.35 h60
  text "X" at 13440,950 h60
  text "SILK" at 13576.46,950.35 h60
  text ".Layer_Name" at 577,-858.49 h60
M11 Gerber Information:
  lines w10: -292,-930.17 6308,-930.17 ; -292,-726.83 6310,-726.83 ; -292,-523.5 -292,-1133.5 3713,-1133.5 6310,-1133.5 6310,-523.5 -291.5,-523.5 -291.5,-1133.5 1284,-1133.5 ; 2173,-1133.5 2173,-523.5 ; 3440,-726.83 3440,-523.5 ; 4280,-726.83 4280,-523.5 ; 4902,-1140 4902,-937.17
  text "ALL ARTWORK VIEWED FROM TOP SIDE" at -228.5,-655.67 h60
  text "BOARD #:" at 2248,-655.67 h60
  text ".PRJ_Number" at 2793.5,-655.67 h60
  text "REV:" at 3638,-655.67 h60
  text ".PCB_Rev" at 3929.5,-655.67 h60
  text "SVN REV:" at 4476,-655.67 h60
  text ".VersionControl_RevNumber" at 4982,-655.67 h60
  text "LAYER NAME =" at -228.5,-858.49 h60
  text "PLOT NAME =" at -228.5,-1064.34 h60
  text ".plot_File_Name" at 577,-1064.34 h60
  text "GENERATED    :" at 2250,-1064.34 h60
  text ".Print_Date" at 3119.5,-1064.34 h60
  text ".Print_Time" at 3848.5,-1064.34 h60
  text "TEXAS INSTRUMENTS" at 5113,-1064.34 h60
M12 Stackup:
  lines w6: 11360,7460 13910,7460 ; 11360,7564.4 13910,7564.4 ; 11300,6975 ccw(c11334,6975) 11334,6941 13936,6941 ccw(c13936,6975) 13970,6975 13970,7681 ccw(c13936,7681) 13936,7715 11334,7715 ccw(c11334,7681) 11300,7681 11300,6975
  text "The Stackup Legend below this is static." at 11605.5,7874.5 h60
  text "If you change the stackup, update the Legend." at 11615.5,7784.5 h60
  text "Layer Stack Up Detail for: Ref_Design.PcbDoc" at 11360,7597.1 h57
  text "Layer" at 11360,7525.4 h24
  text "Gerber" at 12255.81,7525.4 h24
  text "Copper" at 12819.33,7525.4 h24
  text "Dielectric" at 13422.04,7525.4 h24
  text "Name" at 11360,7477.4 h24
  text "Document" at 12255.81,7477.4 h24
  text "Thickness" at 12819.33,7477.4 h24
  text "Material" at 13422.04,7477.4 h24
  text "Top Solder Mask" at 11360,7384.44 h34
  text "(.GTS)" at 12255.81,7384.44 h34
  text "Solder Resist" at 13422.04,7384.44 h34
  text "Top Layer" at 11360,7287.69 h34
  text "(.GTL)" at 12255.81,7287.69 h34
  text "1.4mil" at 12819.33,7287.69 h34
  text "FR-4" at 13422.04,7239.31 h34
  text "Bottom Layer" at 11360,7190.94 h34
  text "(.GBL)" at 12255.81,7190.94 h34
  text "1.4mil" at 12819.33,7190.94 h34
  text "Bottom Solder Mask" at 11360,7094.19 h34
  text "(.GBS)" at 12255.81,7094.19 h34
  text "Solder Resist" at 13422.04,7094.19 h34
  text ".Layer_Name" at 577,-858.49 h60
M13 Component Bodies Top:
  text ".Layer_Name" at 577,-858.49 h60
M14 Component Bodies Bottom:
  text ".Layer_Name" at 577,-858.49 h60
M15 Courtyards Top:
  text ".Layer_Name" at 577,-858.49 h60
M16 Courtyards Bottom:
  text ".Layer_Name" at 577,-858.49 h60
Drill Drawing:
  text ".legend" at 5122.5,725.5 h60
  text "Drill Table" at 5147.5,540.5 h60
  text ".Layer_Name" at 577,-858.49 h60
